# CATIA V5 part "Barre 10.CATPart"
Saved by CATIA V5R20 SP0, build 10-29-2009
Part number: Barre 10
Bounding box of the stored display mesh (mm): x 149.893 to 404.525, y -67.998 to 323.503, z 10 to 20
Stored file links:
  C:\Users\Matthieu\Desktop\IFMA\Cours 2A\Thinkmotion\Projet_IAO_714_Matthieu_Perrusset\Barre 10.CATPart
  C:\Users\Matthieu\Desktop\IFMA\Cours 2A\Thinkmotion\Ass_skl_IAO.CATProduct
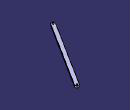
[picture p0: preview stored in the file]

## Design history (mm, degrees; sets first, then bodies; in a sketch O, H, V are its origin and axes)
AxisSystem1: origin (0, 0, 0), X (1, 0, 0), Y (0, 1, 0), Z (0, 0, 1)
Set1
  Plane1 "Plan_Ref": linked copy from another document
  Line1 "Barre_10": linked copy from another document
  Line2 "Axe_Pivot_b10b9": linked copy from another document
  Line3 "Axe_Pivot_b10b11": linked copy from another document
Body1 (main body)
  Sketch1 on Plane1, origin (0, 0, 0), H (1, 0, 0), V (0, 1, 0)
    line L1 (168.2015, -63.4851) -> (403.1247, 308.3068)
    arc A1 centre (394.6709, 313.6485) radius 10 from (403.1247, 308.3068) to (386.2171, 318.9901) ccw
    point P3 (394.6709, 313.6485)
    point P4 (403.1247, 308.3068)
    line L2 (386.2171, 318.9901) -> (151.294, -52.8018)
    arc A2 centre (159.7477, -58.1434) radius 10 from (151.294, -52.8018) to (168.2015, -63.4851) ccw
    point P7 (159.7477, -58.1434)
    reference projected line E1 (394.6709, 313.6485) -> (159.7477, -58.1434) from Line1
    reference projected line E2 (394.6709, 313.6485) -> (159.7477, -58.1434) from Line1
    reference projected line E3 (394.6709, 313.6485) -> (159.7477, -58.1434) from Line1
    reference projected line E4 (394.6709, 313.6485) -> (159.7477, -58.1434) from Line1
    reference projected point E5 (394.6709, 313.6485) from Line2
    reference projected point E6 (159.7477, -58.1434) from Line3
    circle A3 centre (159.7477, -58.1434) radius 5
    circle A4 centre (394.6709, 313.6485) radius 5
    distance L2 E3 = 10
    distance E4 L1 = 10
    distance A1 P3 = 10
    distance P7 A2 = 10
    radius A3 = 5
    radius A4 = 5
    coincidence: A1 P4, P4 L1, E5 P3, P7 E6
    parallelism: L2 L1, E1 L1, L2 E2
  Pad1: profile Sketch1, direction (0, 0, 1), length 20, opposite side length -10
